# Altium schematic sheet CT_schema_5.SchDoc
size 454 x 430 mm
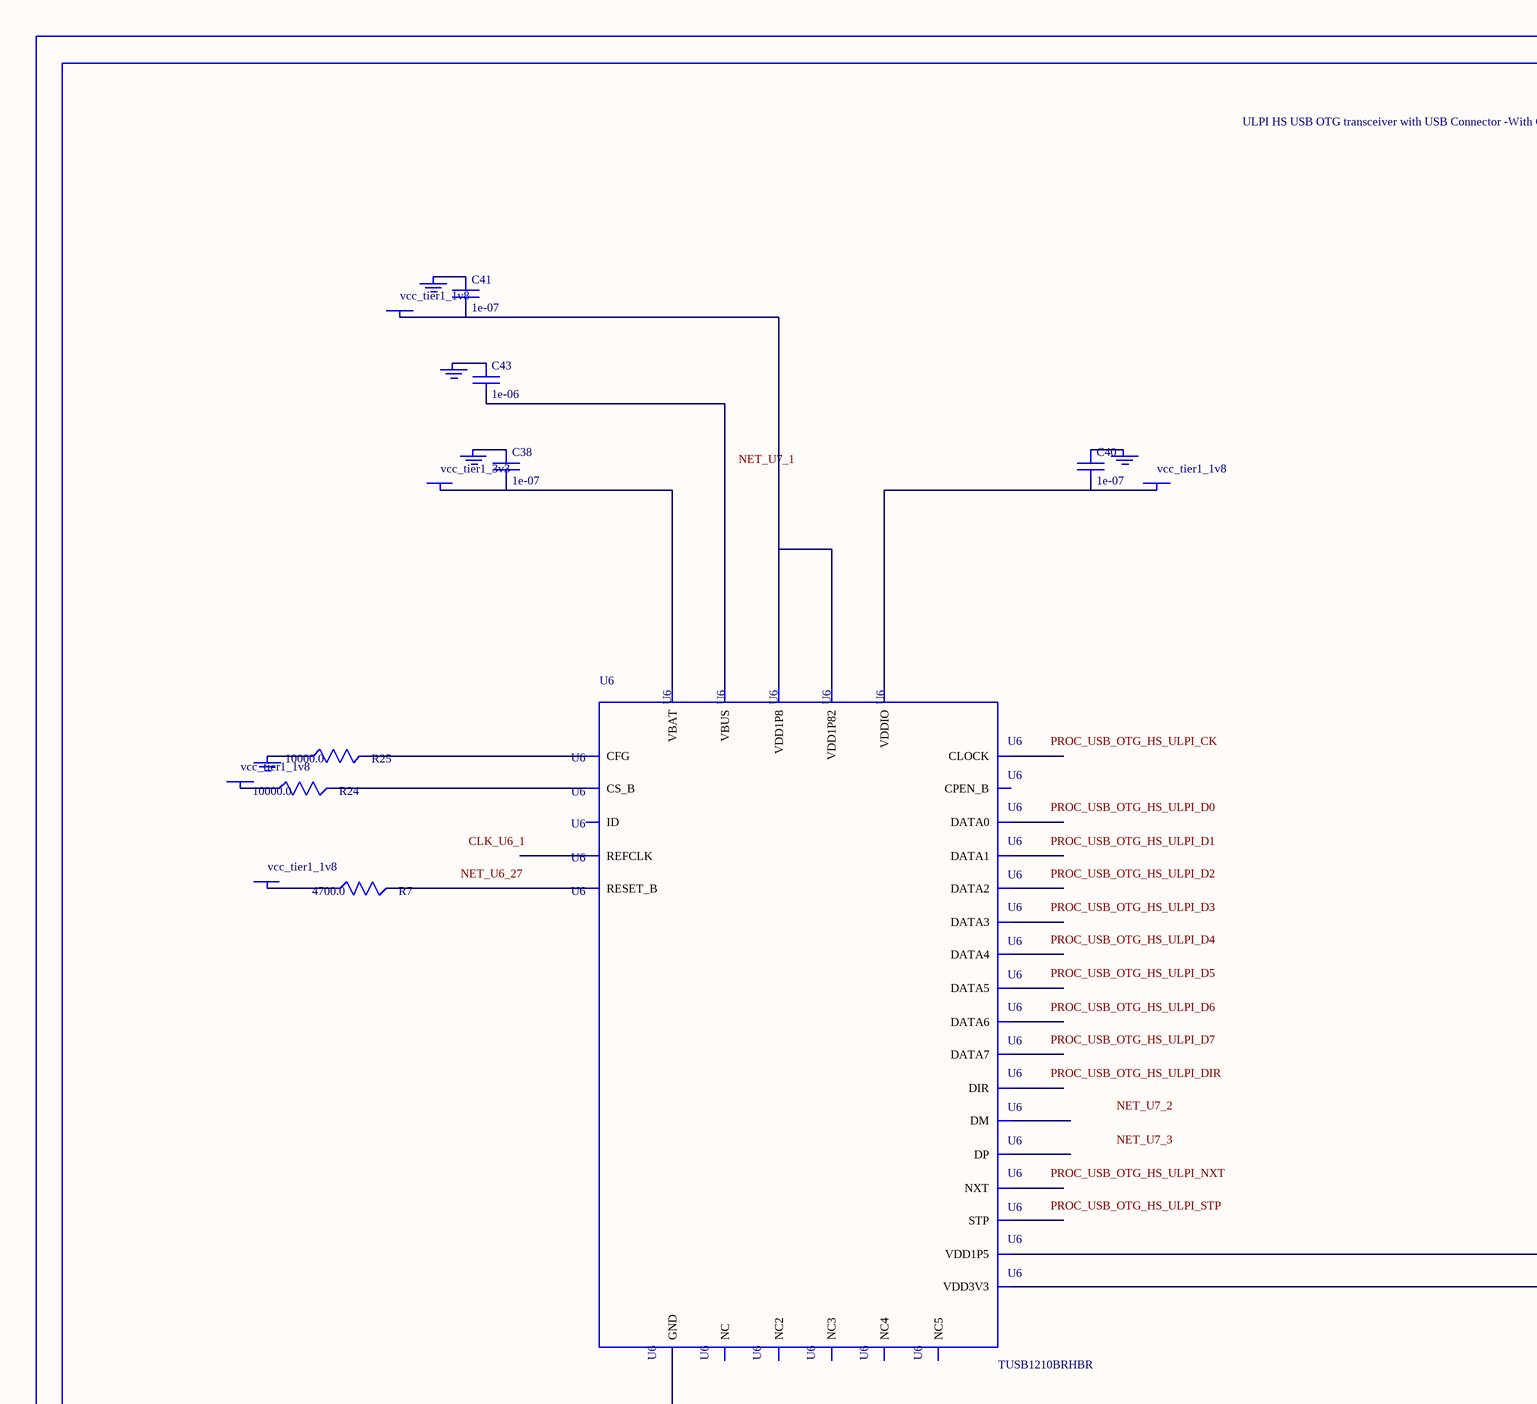
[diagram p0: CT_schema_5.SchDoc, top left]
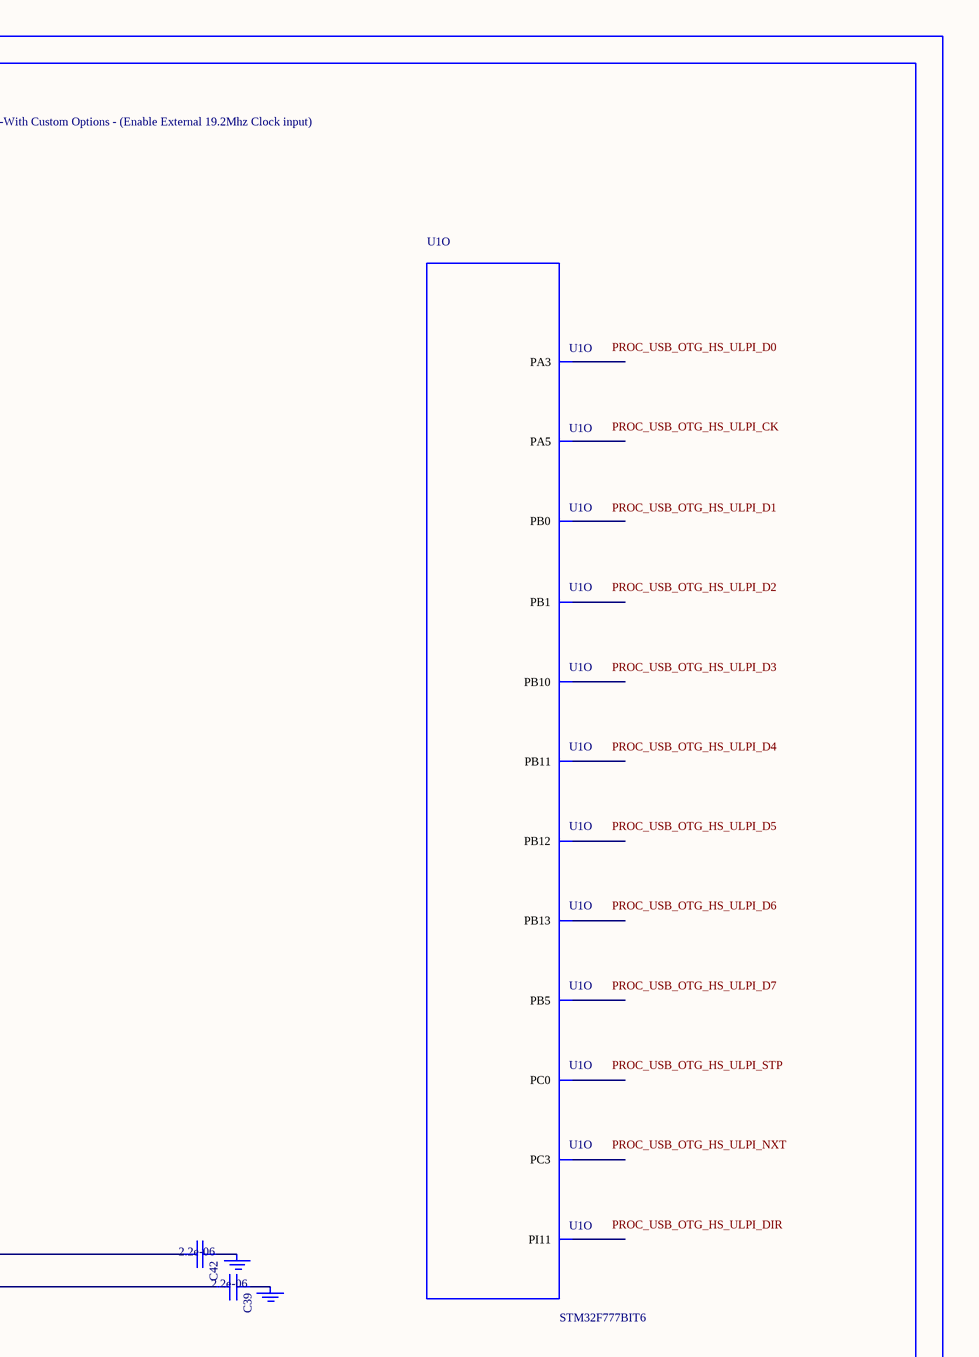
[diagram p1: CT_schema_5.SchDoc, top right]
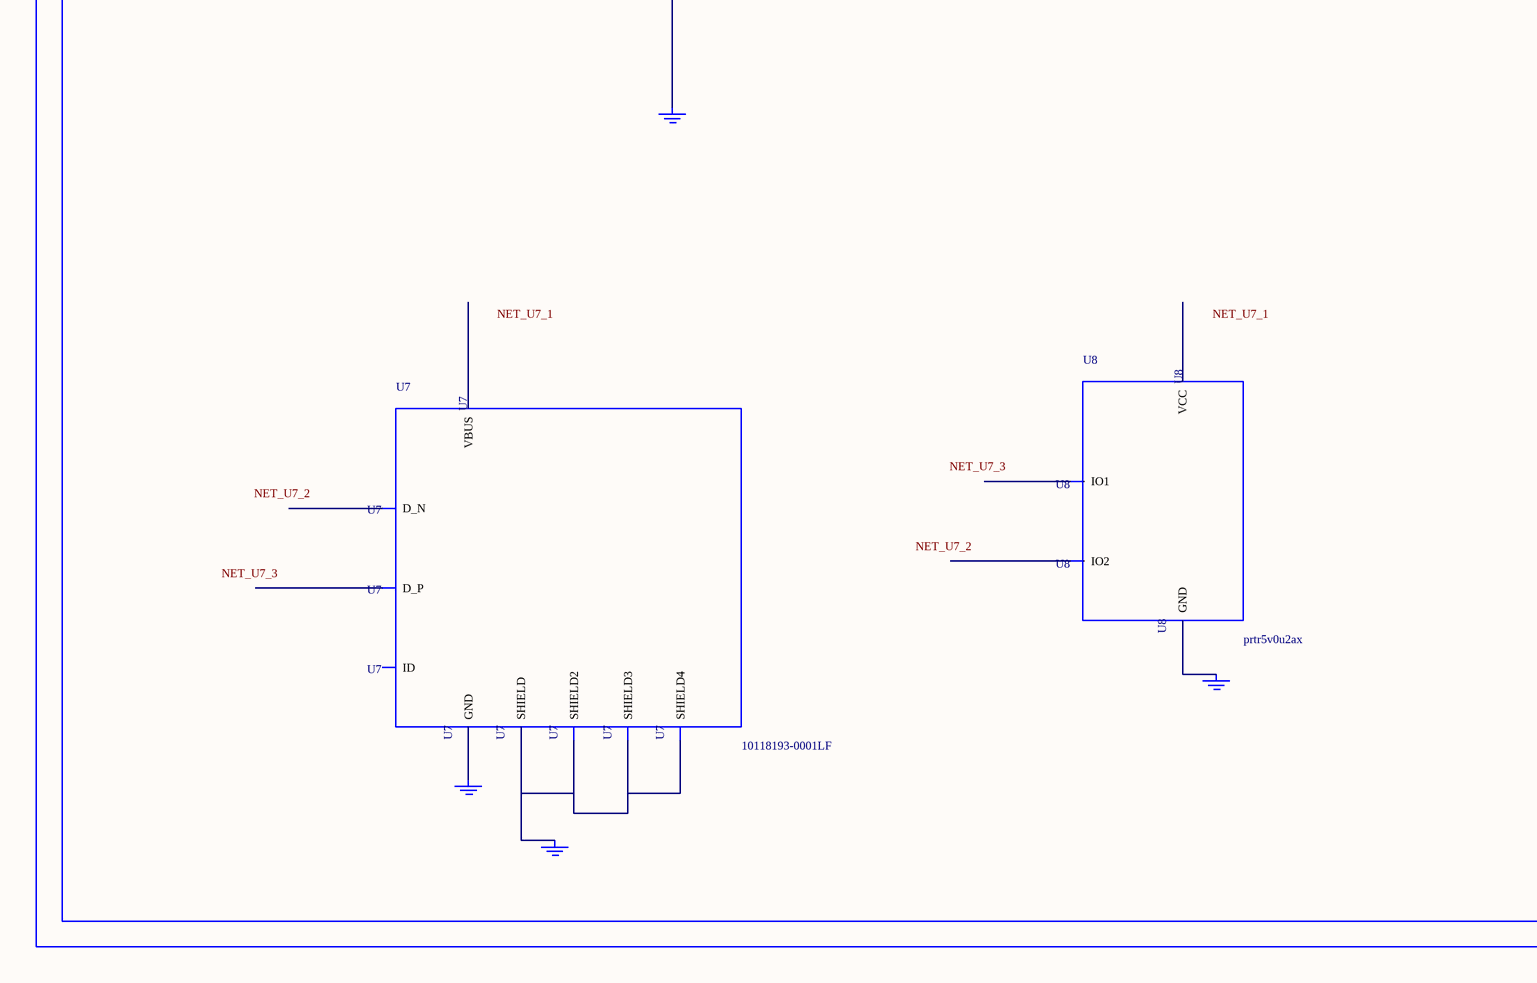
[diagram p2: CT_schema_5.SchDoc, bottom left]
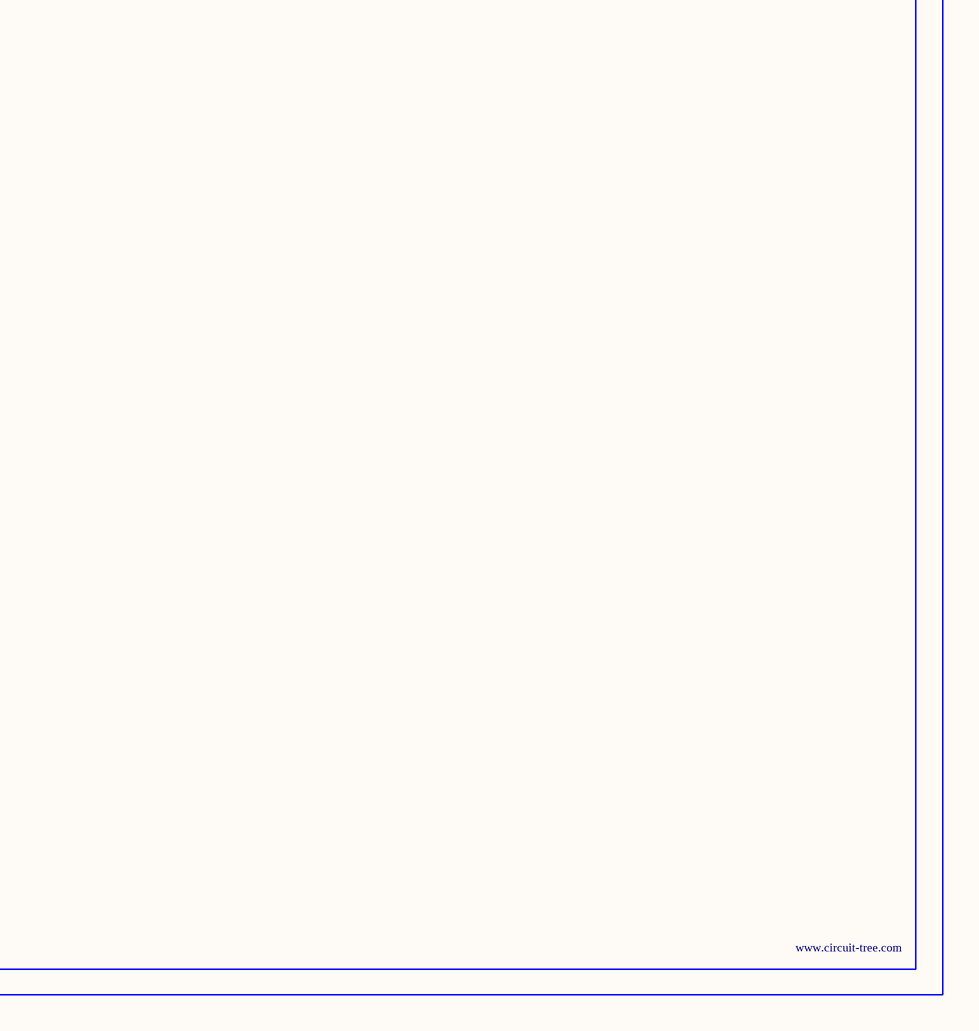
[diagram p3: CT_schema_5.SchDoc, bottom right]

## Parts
BORDER4  (no value)
C38  1e-07  [C0402]
C39  2.2e-06  [C0603]
C40  1e-07  [C0402]
C41  1e-07  [C0402]
C42  2.2e-06  [C0603]
C43  1e-06  [C0603]
GND_INSTANCE_4_0  (no value)
GND_INSTANCE_4_1  (no value)
GND_INSTANCE_4_2  (no value)
GND_INSTANCE_4_3  (no value)
GND_INSTANCE_4_4  (no value)
GND_INSTANCE_4_5  (no value)
GND_INSTANCE_4_6  (no value)
GND_INSTANCE_4_7  (no value)
GND_INSTANCE_4_8  (no value)
GND_INSTANCE_4_9  (no value)
GND_INSTANCE_4_10  (no value)
POWER_INSTANCE_4_0  vcc_tier1_1v8
POWER_INSTANCE_4_1  vcc_tier1_3v3
POWER_INSTANCE_4_2  vcc_tier1_1v8
POWER_INSTANCE_4_3  vcc_tier1_1v8
POWER_INSTANCE_4_4  vcc_tier1_1v8
R7  4700.0  [R0603]
R24  10000.0  [R0603]
R25  10000.0  [R0603]
U1  STM32F777BIT6  [LQFP208]  (part O of 15)
U6  TUSB1210BRHBR  [RHB32_3P45X3P45]
U7  10118193-0001LF  [FCI_10118193-0001LF]
U8  prtr5v0u2ax  [SOT143B]

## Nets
NetC38_1: C38.1 GND_INSTANCE_4_3.0(GND)
NetC38_2: C38.2 POWER_INSTANCE_4_1.0(PWR) U6.21(VBAT)
NetC39_1: C39.1 GND_INSTANCE_4_2.0(GND)
NetC39_2: C39.2 U6.20(VDD3V3)
NetC40_1: C40.1 GND_INSTANCE_4_6.0(GND)
NetC40_2: C40.2 POWER_INSTANCE_4_3.0(PWR) U6.32(VDDIO)
NetC41_1: C41.1 GND_INSTANCE_4_5.0(GND)
NetC41_2: C41.2 POWER_INSTANCE_4_2.0(PWR) U6.28(VDD1P8) U6.30(VDD1P82)
NetC42_1: C42.1 GND_INSTANCE_4_0.0(GND)
NetC42_2: C42.2 U6.12(VDD1P5)
NetC43_1: C43.1 GND_INSTANCE_4_4.0(GND)
NetC43_2: C43.2 U6.22(VBUS)
NetGND_INSTANCE_4_1_0: GND_INSTANCE_4_1.0(GND) R25.1
NetGND_INSTANCE_4_7_0: GND_INSTANCE_4_7.0(GND) U6.33(GND)
NetGND_INSTANCE_4_8_0: GND_INSTANCE_4_8.0(GND) U7.6(SHIELD) U7.7(SHIELD2) U7.8(SHIELD3) U7.9(SHIELD4)
NetGND_INSTANCE_4_9_0: GND_INSTANCE_4_9.0(GND) U7.5(GND)
NetGND_INSTANCE_4_10_0: GND_INSTANCE_4_10.0(GND) U8.1(GND)
NetPOWER_INSTANCE_4_0_0: POWER_INSTANCE_4_0.0(PWR) R24.1
NetPOWER_INSTANCE_4_4_0: POWER_INSTANCE_4_4.0(PWR) R7.1
NetR7_2: R7.2 U6.27(RESET_B)
NetR24_2: R24.2 U6.11(CS_B)
NetR25_2: R25.2 U6.14(CFG)

Not connected (* = marked no-connect by the designer): U1 13(PI11) 35(PC0) 38(PC3) 50(PA3) 54(PA5) 61(PB0) 62(PB1) 90(PB10) 91(PB11) 104(PB12) 105(PB13) 194(PB5); U6 1(REFCLK) 2(NXT) 3(DATA0) 4(DATA1) 5(DATA2) 6(DATA3) 7(DATA4) 8(NC) 9(DATA5) 10(DATA6) 13(DATA7) 15(NC2) 16(NC3) 17(CPEN_B) 18(DP) 19(DM) 23(ID) 24(NC4) 25(NC5) 26(CLOCK) 29(STP) 31(DIR); U7 1(VBUS) 2(D_N) 3(D_P) 4(ID); U8 2(IO1) 3(IO2) 4(VCC)

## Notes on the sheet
- Labels drawn without touching a wire or pin: CLK_U6_1, NET_U6_27, NET_U7_1, NET_U7_2, NET_U7_3, PROC_USB_OTG_HS_ULPI_CK, PROC_USB_OTG_HS_ULPI_D0, PROC_USB_OTG_HS_ULPI_D1, PROC_USB_OTG_HS_ULPI_D2, PROC_USB_OTG_HS_ULPI_D3, PROC_USB_OTG_HS_ULPI_D4, PROC_USB_OTG_HS_ULPI_D5, PROC_USB_OTG_HS_ULPI_D6, PROC_USB_OTG_HS_ULPI_D7, PROC_USB_OTG_HS_ULPI_DIR, PROC_USB_OTG_HS_ULPI_NXT, PROC_USB_OTG_HS_ULPI_STP

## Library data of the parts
BORDER4 = BORDER_PAGE4
C38 C40 C41 = C0402C104K3RACTU
C39 C42 = C0603C225K8RACTU
C43 = C0603C105K3RACTU
GND_INSTANCE_4_0-GND_INSTANCE_4_10 = GND
POWER_INSTANCE_4_0-POWER_INSTANCE_4_4 = PWR
R7 = RC0603JR-074K7L
R24 R25 = RC0603JR-0710KL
